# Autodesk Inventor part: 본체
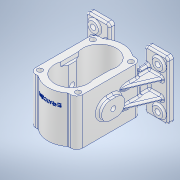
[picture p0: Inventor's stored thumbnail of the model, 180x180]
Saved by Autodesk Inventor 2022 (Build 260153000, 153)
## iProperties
Created: 2023-06
Part Number: 본체
Material: 알루미늄 6061
Document SubType Name: Modeling
Designer: PC-03
Density: 2.7 g/cm^3
Appearance: 알루미늄 - 평지
Mass: 1176.69 g
Surface Area: 976.867 cm^2
Volume: 435.809 cm^3
Author: PC-03
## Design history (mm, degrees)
sketch "스케치4"
  geometry: L1 (-70, 50)-(-30, 50); L2 (-30, 50)-(-30, -50); L3 (-30, -50)-(-70, -50); L4 (-70, -50)-(-70, 50); L5 (-70, 50)-(-30, -50); L6 (-30, 50)-(-70, -50); L7 (30, 50)-(70, 50); L8 (70, 50)-(70, -50); L9 (70, -50)-(30, -50); L10 (30, -50)-(30, 50); L11 (30, 50)-(70, -50); L12 (70, 50)-(30, -50); L13 (-98, 0)-(98, 0) reference; L14 (0, -70)-(0, 70) reference; 3 further points
  constraints: 24 end point, 4 midpoint, 4 parallel, 3 symmetric about line, 2 horizontal, 2 perpendicular, 1 point on line
  dimensions: "d16" = 40 distance of L1.start L1.end; "d17" = 100 distance of L3.end L1.start; "d18" = 140 distance between parallel lines of L8 L4
extrude "돌출3" new body sketch "스케치4" distance "d19" = 9; taper "d20" = 0 deg
sketch "스케치5"
  geometry: L1 (-98, 0)-(98, 0) reference; L2 (-55, 83)-(-55, -67.41); L3 (0, -106.516)-(0, 114.586) reference; L4 (55, 81.496)-(55, -74.93); C1 r 9 at (-55, 35); C2 r 9 at (-55, -35); C3 r 9 at (55, 35); C4 r 9 at (55, -35); 1 further point
  constraints: 4 centre point, 4 end point, 2 point on line, 2 symmetric about line, 2 vertical, 1 other
  dimensions: "d21" = 18 diameter of C1; "d23" = 110 distance between parallel lines of L4 L2; "d24" = 70 distance of C2.centre C1.centre; "d25" = 70 distance of C4.centre C3.centre; "d26" = 18 diameter of C2; "d27" = 18 diameter of C4; "d28" = 18 diameter of C3
extrude "돌출4" join sketch "스케치5" distance "d29" = 3; taper "d30" = 0 deg
sketch "스케치6"
  geometry: C1 r 4.5 at (0, 0); C2 r 9 at (0, 0) reference; 1 further point
  constraints: 1 centre point, 1 coincident
  dimensions: "d31" = 9 diameter of C1
extrude "돌출5" cut sketch "스케치6" extent not by distance; stored distance "d32" = 50; taper "d33" = 0 deg
sketch "스케치7"
  geometry: L1 (0, 129.709)-(0, 30.291); L2 (0, -28.8)-(0, 172.8) reference; L3 (73.621, 80)-(-78.887, 80); L4 (-30, 0)-(-70, 0) reference; L5 (40, 135)-(-40, 135); L6 (-40, 135)-(-40, 25); L7 (-40, 25)-(40, 25); L8 (40, 25)-(40, 135); L9 (40, 135)-(-40, 25); L10 (-40, 135)-(40, 25); C1 r 40 at (0, 104); C2 r 40 at (0, 56); 6 further points
  constraints: 18 end point, 4 point on line, 3 midpoint, 2 centre point, 2 horizontal, 2 parallel, 1 perpendicular, 1 symmetric about line, 1 tangent, 1 vertical
  dimensions: "d34" = 80 distance between parallel lines of L4 L3; "d36" = 80 diameter of C2; "d37" = 80 diameter of C1; "d38" = 48 distance of C2.centre C1.centre; "d39" = 110 distance of L5.end L6.end
extrude "돌출6" join sketch "스케치7" stored distance "d40" = 79; taper "d41" = 0 deg
sketch "스케치9"
  geometry: L1 (-30, -50)-(-30, 50) reference; L2 (-38, 25)-(-30, 25); L3 (-30, 25)-(-30, -25); L4 (-30, -25)-(-38, -25); L5 (-38, -25)-(-38, 25); L6 (-98, 0)-(98, 0) reference; 1 further point
  constraints: 8 end point, 2 parallel, 1 horizontal, 1 perpendicular, 1 point on line, 1 other
  dimensions: "d45" = 50 distance of L4.end L2.start; "d46" = 8 distance of L2.start L2.end
extrude "돌출7" join sketch "스케치9" stored distance "d47" = 40; taper "d48" = 0 deg
sketch "스케치10"
  geometry: L1 (62, 9)-(40, 60.829); L2 (40, 25)-(40, 135) reference; L3 (70, 0)-(70, 9) reference; L4 (30, 9)-(70, 9) reference; 3 further points
  constraints: 2 end point, 2 point on line
  dimensions: "d49" = 23 deg angle of L3 L1; "d50" = 8 distance from line of L3 L1.start
feature "리브1" sketch "스케치10" dims "d51" = 1, "d52" = 36, "d53" = 0, "d54" = 0, "d55" = 1, "d56" = 1
sketch "스케치11"
  geometry: L1 (40, 25)-(40, 60.829) reference; L2 (38, 25)-(40, 25) reference; L3 (38, 9)-(38, 25) reference; L4 (62, 9)-(38, 9) reference; L5 (40, 60.829)-(62, 9) reference; L6 (62, 9)-(40, 60.829); L7 (40, 25)-(40, 135) reference; L8 (40, 60.829)-(40, 25); L9 (38, 25)-(40, 25) reference; L10 (40, 25)-(38, 25); L11 (38, 9)-(38, 25) reference; L12 (38, 25)-(38, 9); L13 (38, 9)-(62, 9); 1 further point
  constraints: 10 end point, 2 collinear, 2 perpendicular
extrude "돌출8" cut sketch "스케치11" stored distance "d57" = 22; taper "d58" = 0 deg
sketch "스케치12"
  geometry: L1 (0, 85)-(0, 75); L2 (15, 85)-(15, 75); L3 (-15, 75)-(-15, 85); L4 (0, -28.8)-(0, 172.8) reference; L5 (50, 0)-(-50, 0) reference; A1 r 15 centre (0, 85) between (15, 85) and (-15, 85); A2 r 15 centre (0, 75) between (-15, 75) and (15, 75); 2 further points
  constraints: 8 end point, 4 point on circle, 4 tangent, 2 centre point, 1 midpoint, 1 parallel, 1 point on line, 1 vertical
  dimensions: "d59" = 30 distance between parallel lines of L3 L2; "d60" = 80 distance from line of L5 point (0, 80); "d61" = 10 distance of L1.start L1.end
extrude "돌출9" join sketch "스케치12" stored distance "d62" = 95; taper "d63" = 0 deg
sketch "스케치14" dims "d68" = 57
  geometry: L1 (0, 28.8)-(0, -172.8) reference; L2 (62.711, -80)-(-77.674, -80); L3 (-30, 0)-(-70, 0) reference; L4 (22.5, -86.507)-(-22.5, -86.507); L5 (-22.5, -86.507)-(-22.5, -73.493); L6 (-22.5, -73.493)-(22.5, -73.493); L7 (22.5, -73.493)-(22.5, -86.507); L8 (22.5, -86.507)-(-22.5, -73.493); L9 (-22.5, -86.507)-(22.5, -73.493); C1 r 28.5 at (0, -104); 6 further points
  constraints: 14 end point, 4 point on line, 2 horizontal, 2 midpoint, 2 parallel, 1 centre point, 1 perpendicular, 1 symmetric about line, 3 other
  dimensions: "d65" = 80 distance between parallel lines of L3 L2; "d66" = 48 distance of point (0, -56) C1.centre; "d67" = 57 diameter of C1; "d69" = 45 distance of L4.start L4.end
extrude "돌출10" cut sketch "스케치14" extent not by distance; stored distance "d70" = 0; taper "d71" = 0 deg
sketch "스케치15"
  geometry: L1 (27, -104)-(22.5, -104); L2 (22.5, -104)-(22.5, -56); L3 (22.5, -56)-(27, -56); L4 (27, -56)-(27, -104); L5 (67.864, -80)-(-92.433, -80); L6 (-30, 0)-(-70, 0) reference; 2 further points
  constraints: 10 end point, 2 horizontal, 2 parallel, 1 perpendicular, 1 point on line, 1 other
  dimensions: "d72" = 80 distance between parallel lines of L6 L5; "d73" = 48 distance of L1.end L2.end; "d74" = 4.5 distance of L1.start L1.end
extrude "돌출11" cut sketch "스케치15" distance "d75" = 7; taper "d76" = 0 deg
sketch "스케치16"
  geometry: L1 (89.655, -80)-(-117.61, -80); L2 (-30, 0)-(-70, 0) reference; L3 (0, 28.8)-(0, -172.8) reference; C1 r 4.5 at (32.5, -125); C2 r 4.5 at (-32.5, -125); C3 r 4.5 at (32.5, -35); C4 r 4.5 at (-32.5, -35); 1 further point
  constraints: 4 centre point, 3 symmetric about line, 2 end point, 1 horizontal
  dimensions: "d77" = 80 distance between parallel lines of L2 L1; "d78" = 65 distance of C2.centre C1.centre; "d79" = 90 distance of C3.centre C1.centre; "d80" = 9 diameter of C1; "d81" = 9 diameter of C2; "d82" = 9 diameter of C4; "d83" = 9 diameter of C3
extrude "돌출12" cut sketch "스케치16" extent not by distance; stored distance "d84" = 0; taper "d85" = 0 deg
sketch "스케치17"
  geometry: L1 (80, 84.854)-(80, -90.502); L2 (0, 50)-(0, -50) reference; L3 (-28.8, 0)-(172.8, 0) reference; 2 further points
  constraints: 2 end point, 2 point on line, 1 vertical
  dimensions: "d86" = 80 distance between parallel lines of L2 L1
hole "구멍1" sketch "스케치17" at (80, 0) diameter "d87" = 8.376; stored, may be unused: countersink angle "d91" = 90 deg, drill point angle "d93" = 0 deg; dims "d88" = 10, "d89" = 4, "d90" = 2, "d92" = 27.3
fillet "모깎기1" dims "d94" = 5
fillet "모깎기2" dims "d95" = 10
fillet "모깎기4" dims "d97" = 3
fillet "모깎기5" dims "d98" = 3
fillet "모깎기7" dims "d100" = 3
fillet "모깎기8" dims "d101" = 3
fillet "모깎기9" dims "d102" = 3
sketch "스케치19"
  geometry: C1 r 4.5 at (0, 0); C2 r 4.5 at (0, 0) reference; 1 further point
  constraints: 1 centre point, 1 coincident
  dimensions: "d104" = 9 diameter of C1
extrude "돌출13" cut sketch "스케치19" extent not by distance; stored distance "d105" = 0; taper "d106" = 0 deg
node "작업 평면1"
sketch "스케치20"
  geometry: L1 (0, -70)-(0, 70) reference; L2 (-98, 0)-(98, 0) reference; 2 further points
  constraints: 1 point on line, 1 other
  dimensions: "d108" = 20 distance from line of L2 point (0, 20)
feature "엠보싱1" sketch "스케치20" dims "d16" = 40, "d17" = 100, "d18" = 140, "d21" = 18, "d23" = 110, "d24" = 70, "d25" = 70, "d26" = 18, "d27" = 18, "d28" = 18, "d109" = 0.5, "d110" = 0
node "솔리드2"
mirror "미러1"
mirror "미러2"
mirror "미러3"
mirror "미러4"
mirror "미러5"
mirror "미러6"
mirror "미러7"
node "투영된 루프1"
node "투영된 루프2"
node "투영된 루프3"
feature "A9D066F2-1C7D-4E18-AEED-F7BC21143FA4" dims "d87" = 8.376, "d88" = 10, "d89" = 4, "d90" = 2, "d91" = 90 deg, "d92" = 27.3, "d93" = 0
other parameters: "d107" = 144
